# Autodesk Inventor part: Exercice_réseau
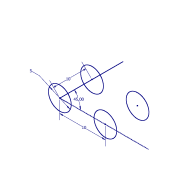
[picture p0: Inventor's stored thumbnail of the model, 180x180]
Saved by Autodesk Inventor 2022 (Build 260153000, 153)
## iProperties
Created: 2021-05
Part Number: Exercice_réseau
Material: Générique
Document SubType Name: Modeling
Designer: Fabian
Density: 1 g/cm^3
Appearance: Par défaut
Author: Fabian
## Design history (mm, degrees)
sketch "Esquisse1"
  geometry: L1 (0, 0)-(19.365, 0); L2 (0, 0)-(13.889, 13.889); L3 (0, 0)-(19.642, 0); C1 r 2.5 at (0, 0); C2 r 2.5 at (7.071, 7.071); C3 r 2.5 at (10, 0); C4 r 2.5 at (17.071, 7.071); 1 further point
  constraints: 6 end point, 4 centre point, 3 horizontal, 2 coincident, 1 equal length, 7 other
  dimensions: "d11" = 45 deg angle of L3 L2; "d12" = 5 diameter of C1; "d15" = 10 distance of C1.centre C2.centre; "d18" = 10 distance of C1.centre C3.centre
